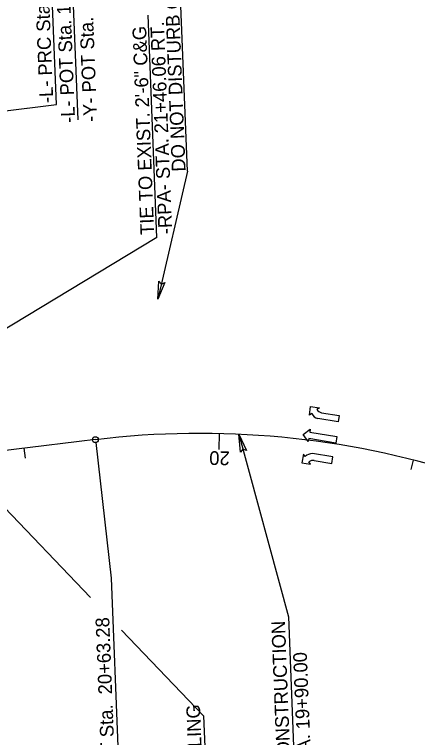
# Model space of a CAD drawing. Extents: x 1627861 to 1629601, y 761281 to 766239.
# Drawn here: x 1628584.8 to 1628790.4, y 761565 to 761933.4 of the extents above; entities that cross this region are included whole.
import ezdxf

# ---------------------------------------------------------------- set-up
doc = ezdxf.new("R2010")
doc.units = 0
for name, color, linetype in [('Exist Other Culture Sign Leader', 7, 'Continuous'), ('Exist Property Tie Line Leader', 7, 'Continuous'), ('Exist Property Tie Line Text', 7, 'Continuous'), ('Exist Right of Way Line Leader', 7, 'Continuous'), ('Exist Right of Way Monument Leader', 7, 'Continuous'), ('Exist Utilities Gas Meter CELL', 7, 'Continuous'), ('Exist Utilities Gas Meter Cogo Number', 7, 'Continuous'), ('Exist Utilities Power UG Cable SUE LOS B Cogo Point CELL', 7, 'Continuous'), ('Exist Utilities Water Meter Cogo Elevation', 7, 'Continuous'), ('Scratch_Level_0', 7, 'Continuous')]:
    doc.layers.add(name, color=color, linetype=linetype)

# ---------------------------------------------------------------- blocks, each defined once
blk = doc.blocks.new('Lane Arrow Left Turn')
at = {"layer": 'Exist Right of Way Monument Leader'}
for p, q in [((0, 0), (-4.5, 0.05)), ((-4.5, 0.05), (-3.45, -1)), ((-5.95, -2.15), (-15.1, -2.15)), ((-15.1, -2.15), (-15.1, -5.45)), ((-1.1, -3.35), (-0.05, -4.4)), ((-0.05, -4.4), (0, 0)), ((-15.1, -5.45), (-4.55, -5.45))]:
    blk.add_line(p, q, dxfattribs=at)
for centre, radius, start, end in [((-5.94, 1.11), 3.27, 270, 319.6582), ((-5.34, -0.27), 5.25, 278.6761, 323.9878)]:
    blk.add_arc(centre, radius, start, end, dxfattribs=at)

msp = doc.modelspace()

# ---------------------------------------------------------------- linework, layer by layer
at = {"layer": 'Exist Property Tie Line Text'}
for p, q in [((1628589.65, 761712.37), (1628590.25, 761707.41)), ((1628788.14, 761706.39), (1628786.91, 761701.54))]:
    msp.add_line(p, q, dxfattribs=at)
at = {"layer": 'Exist Right of Way Line Leader'}
for p, q in [((1628606.22, 761887.58), (1628601.66, 762003.32)), ((1628617.3, 761879.65), (1628612.77, 761994.56)), ((1628491.24, 761873.08), (1628606.22, 761887.58)), ((1628626.29, 761715.28), (1628634.23, 761646.28)), ((1628634.23, 761646.28), (1628639.11, 761522.47))]:
    msp.add_line(p, q, dxfattribs=at)
msp.add_circle((1628626.11, 761716.77), 1.5, dxfattribs=at)
at = {"layer": 'Exist Right of Way Monument Leader'}
for p, q in [((1628735.2, 761729.24), (1628735.86, 761733.6)), ((1628735.86, 761733.6), (1628740.31, 761732.92)), ((1628740.31, 761732.92), (1628739.1, 761732.05)), ((1628741.39, 761730.52), (1628750.42, 761729.05)), ((1628736.41, 761730.11), (1628735.2, 761729.24)), ((1628749.89, 761725.79), (1628739.48, 761727.49)), ((1628750.42, 761729.05), (1628749.89, 761725.79)), ((1628732.02, 761719.39), (1628735.64, 761722.05)), ((1628734.63, 761715.83), (1628732.02, 761719.39)), ((1628735.64, 761722.05), (1628735.4, 761720.56)), ((1628735.4, 761720.56), (1628749.22, 761718.32)), ((1628734.87, 761717.31), (1628734.63, 761715.83)), ((1628748.69, 761715.06), (1628734.87, 761717.31)), ((1628749.22, 761718.32), (1628748.69, 761715.06))]:
    msp.add_line(p, q, dxfattribs=at)
for centre, radius, start, end in [((1628741.9, 761733.74), 3.27, 211.1065, 260.7647), ((1628741.09, 761732.47), 5.25, 206.7769, 252.0886)]:
    msp.add_arc(centre, radius, start, end, dxfattribs=at)
at = {"layer": 'Exist Utilities Gas Meter CELL'}
msp.add_line((1628626.11, 761716.77), (1628491.37, 761700.53), dxfattribs=at)
msp.add_arc((1628679.23, 761275.95), 444, 48.0133, 96.871, dxfattribs=at)
at = {"layer": 'Exist Utilities Gas Meter Cogo Number'}
for points in [[(1628661.56, 761796.75), (1628658.03, 761788.33), (1628658.5, 761797.51), (1628659.8, 761796.03)], [(1628700.12, 761710.41), (1628699.26, 761719.5), (1628703.18, 761711.19), (1628701.33, 761711.88)]]:
    msp.add_lwpolyline(points, close=True, dxfattribs=at)
at = {"layer": 'Exist Utilities Water Meter Cogo Elevation'}
msp.add_line((1628689.26, 761719.84), (1628689.08, 761711.84), dxfattribs=at)
at = {"layer": 'Scratch_Level_0'}
for p, q in [((1628673.06, 761853.53), (1628667.61, 761991.62)), ((1628657.43, 761819.78), (1628652.96, 761933.03)), ((1628673.06, 761853.53), (1628658.03, 761788.33)), ((1628657.43, 761819.78), (1628538.95, 761748.22)), ((1628699.26, 761719.5), (1628724.58, 761626.53)), ((1628554.9, 761708.18), (1628623.54, 761636.44)), ((1628724.58, 761626.53), (1628728.88, 761517.35)), ((1628639.49, 761619.77), (1628681.22, 761576.16)), ((1628681.22, 761576.16), (1628686.67, 761437.91))]:
    msp.add_line(p, q, dxfattribs=at)

# ---------------------------------------------------------------- block references
at = {"layer": 'Exist Right of Way Monument Leader', "rotation": 170.69842902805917}
msp.add_blockref('Lane Arrow Left Turn', (1628731.43, 761705.01), dxfattribs=at)

# ---------------------------------------------------------------- texts
at = {"layer": 'Exist Other Culture Sign Leader'}
for s, p in [('BEGIN CONSTRUCTION', (1628726.97, 761517.55)), ('-RPA- STA. 19+90.00', (1628737.46, 761517.96)), ('BEGIN RESURFACING/MILLING', (1628684.92, 761442.28))]:
    msp.add_text(s, height=7, rotation=92.2582, dxfattribs=at).set_placement(p)
at = {"layer": 'Exist Property Tie Line Leader'}
msp.add_text('20', height=7, rotation=178.7053, dxfattribs=at).set_placement((1628694.68, 761710.72))
at = {"layer": 'Exist Right of Way Line Leader'}
for s, p in [('-L- PRC Sta.  13+97.40', (1628604.67, 761888.35)), ('-L- POT Sta. 16+45.75=', (1628615.8, 761878.29)), ('-Y- POT Sta.  10+00.00', (1628627.06, 761878.74)), ('-RPA- PT Sta.  20+63.28', (1628637.22, 761522.71))]:
    msp.add_text(s, height=7, rotation=92.2582, dxfattribs=at).set_placement(p)
at = {"layer": 'Exist Utilities Power UG Cable SUE LOS B Cogo Point CELL'}
for s, p in [('DO NOT DISTURB C/A FENCE', (1628672.12, 761853.44)), ('TIE TO EXIST. 2\'-6" C&G', (1628656.14, 761821.21)), ('-RPA- STA. 21+46.06 RT.', (1628665.31, 761821.57))]:
    msp.add_text(s, height=7, rotation=92.2582, dxfattribs=at).set_placement(p)

doc.saveas('drawing.dxf')
